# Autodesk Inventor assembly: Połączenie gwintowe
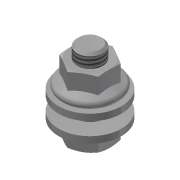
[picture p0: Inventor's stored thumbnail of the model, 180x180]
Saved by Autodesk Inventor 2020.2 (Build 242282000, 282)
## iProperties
Manager: www.cadconsulting.pl
Company: Fabian Stasiak CAD Consulting
ClientObjectVersion: 1
Created: 2011-01
Part Number: Połączenie gwintowe
Document SubType Name: Assembly
Designer: F.Stasiak
Author: F.Stasiak
Subject: Zbiór ćwiczeń. Autodesk Inventor 2020. Kurs podstawowy
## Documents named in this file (4)
- C:\2020_Kurs_podstawowy\R6 Zespoły\Kolizja\100-000\Design Accelerator\Połączenie gwintowe5.iam
- C:\2020_Kurs_podstawowy\Zasoby\Content Center Files\pl-PL\DIN 6796\DIN 6796 - 12.ipt
- C:\2020_Kurs_podstawowy\Zasoby\Content Center Files\pl-PL\DIN EN 24 017\ISO 4017 - M12 x 30DIN EN.ipt
- C:\2020_Kurs_podstawowy\Zasoby\Content Center Files\pl-PL\DIN 6923\DIN 6923 - M12 x 1,75.ipt
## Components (4 placed, 3 different names)
1. DIN 6796 12:1
2. DIN EN 24017 M12 x 30:1
3. DIN 6796 12:2
4. DIN 6923 M12:1
